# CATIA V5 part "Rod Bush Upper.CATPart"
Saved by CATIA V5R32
Part number: Rod Bush Upper
Bounding box of the stored display mesh (mm): x -12 to 12, y -11.818 to 11.818, z -21 to 21
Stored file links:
  D:\PROJECTS\Project 2022\CATIA V5 6R 2022\Resources\Part Files\c13_catia_v5_6r2022_prt\c13_catia_v5-6r2022_figr_13-41\Part & Asm files\Rod Bush Upper.CATPart
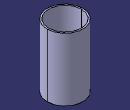
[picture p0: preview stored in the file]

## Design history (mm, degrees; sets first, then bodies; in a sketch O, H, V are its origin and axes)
Body1 (main body)
  Sketch1 on xy-plane, origin (0, 0, 0), H (1, 0, 0), V (0, 1, 0)
    circle A1 centre (0, 0) radius 11
    circle A2 centre (0, 0) radius 12
    point P1 (0, 0)
    radius A2 = 12
    radius A1 = 11
    coincidence: P1 H
    concentricity: A1 A2
  Pad1: profile Sketch1, direction (0, 0, 1), length 21, mirrored extent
